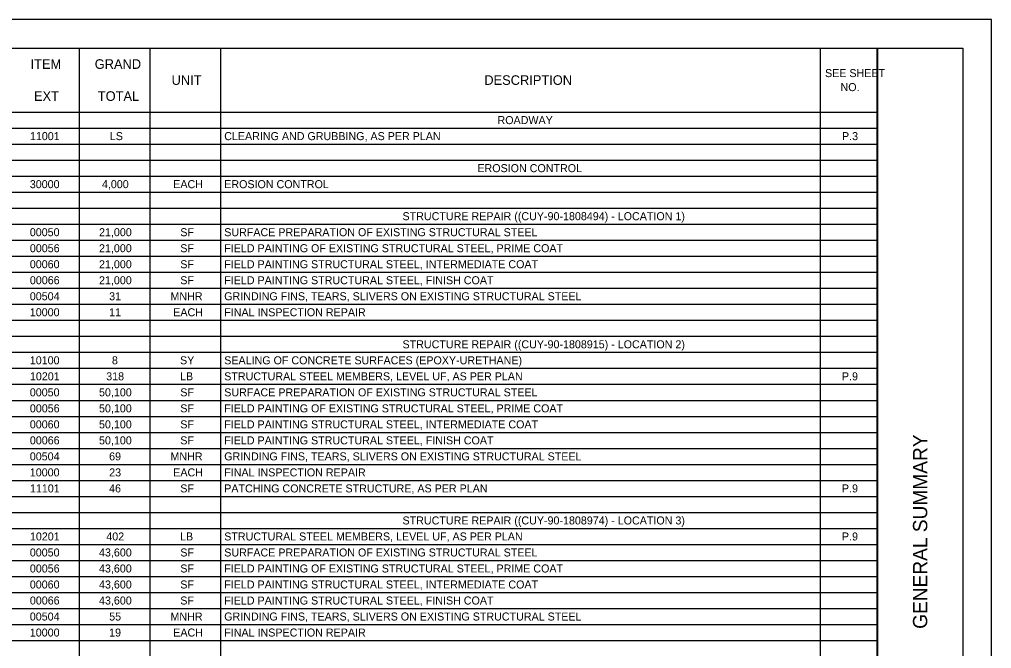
# Model space of a CAD drawing. Extents: x 0 to 34, y 0 to 22.
# Drawn here: x 16.99 to 34, y 11 to 22 of the extents above; entities that cross this region are included whole.
import ezdxf

# ---------------------------------------------------------------- set-up
doc = ezdxf.new("R2010")
doc.units = 0
for name, color, linetype in [('SH_Border', 7, 'Continuous'), ('SH_Cut_Line', 7, 'Continuous'), ('SH_Data', 7, 'Continuous'), ('SH_Text', 7, 'Continuous')]:
    doc.layers.add(name, color=color, linetype=linetype)

msp = doc.modelspace()

# ---------------------------------------------------------------- linework, layer by layer
at = {"layer": 'SH_Border'}
msp.add_line((32, 0.5), (32, 21.5), dxfattribs=at)
msp.add_lwpolyline([(1.5, 21.5), (33.5, 21.5), (33.5, 0.5), (1.5, 0.5)], close=True, dxfattribs=at)
at = {"layer": 'SH_Cut_Line'}
msp.add_lwpolyline([(0, 0), (34, 0), (34, 22), (0, 22)], close=True, dxfattribs=at)
at = {"layer": 'SH_Data'}
for p, q in [((1.5, 21.5), (32.004, 21.5)), ((18.036, 21.5), (18.036, 0.5)), ((19.272, 21.5), (19.272, 0.5)), ((20.507, 21.5), (20.507, 0.5)), ((30.999, 21.5), (30.999, 0.5)), ((32.004, 21.5), (32.004, 0.5)), ((1.5, 20.38), (32.004, 20.38)), ((1.5, 20.1), (32.004, 20.1)), ((1.5, 19.82), (32.004, 19.82)), ((1.5, 19.54), (32.004, 19.54)), ((1.5, 19.26), (32.004, 19.26)), ((1.5, 18.98), (32.004, 18.98)), ((1.5, 18.7), (32.004, 18.7)), ((1.5, 18.42), (32.004, 18.42)), ((1.5, 18.14), (32.004, 18.14)), ((1.5, 17.86), (32.004, 17.86)), ((1.5, 17.58), (32.004, 17.58)), ((1.5, 17.3), (32.004, 17.3)), ((1.5, 17.02), (32.004, 17.02)), ((1.5, 16.74), (32.004, 16.74)), ((1.5, 16.46), (32.004, 16.46)), ((1.5, 16.18), (32.004, 16.18)), ((1.5, 15.9), (32.004, 15.9)), ((1.5, 15.62), (32.004, 15.62)), ((1.5, 15.34), (32.004, 15.34)), ((1.5, 15.06), (32.004, 15.06)), ((1.5, 14.78), (32.004, 14.78)), ((1.5, 14.5), (32.004, 14.5)), ((1.5, 14.22), (32.004, 14.22)), ((1.5, 13.94), (32.004, 13.94)), ((1.5, 13.66), (32.004, 13.66)), ((1.5, 13.38), (32.004, 13.38)), ((1.5, 13.1), (32.004, 13.1)), ((1.5, 12.82), (32.004, 12.82)), ((1.5, 12.54), (32.004, 12.54)), ((1.5, 12.26), (32.004, 12.26)), ((1.5, 11.98), (32.004, 11.98)), ((1.5, 11.7), (32.004, 11.7)), ((1.5, 11.42), (32.004, 11.42)), ((1.5, 11.14), (32.004, 11.14))]:
    msp.add_line(p, q, dxfattribs=at)

# ---------------------------------------------------------------- texts
msp.add_text('GENERAL SUMMARY', height=0.25, rotation=90, dxfattribs=at).set_placement((32.875, 11.344))
at = {"layer": 'SH_Text'}
for s, height, p in [('ITEM', 0.168, (17.184, 21.136)), ('GRAND', 0.168, (18.307, 21.136)), ('SEE SHEET ', 0.14, (31.086, 20.992)), ('UNIT', 0.168, (19.652, 20.856)), ('DESCRIPTION', 0.168, (25.124, 20.856)), ('NO.', 0.14, (31.357, 20.747)), ('EXT', 0.168, (17.244, 20.576)), ('TOTAL', 0.168, (18.361, 20.576)), ('ROADWAY', 0.14, (25.355, 20.17)), ('11001', 0.14, (17.173, 19.89)), ('LS', 0.14, (18.572, 19.89)), ('CLEARING AND GRUBBING, AS PER PLAN', 0.14, (20.573, 19.89)), ('P.3', 0.14, (31.383, 19.89)), ('EROSION CONTROL', 0.14, (25.003, 19.33)), ('30000', 0.14, (17.171, 19.05)), ('4,000', 0.14, (18.433, 19.05)), ('EACH', 0.14, (19.681, 19.05)), ('EROSION CONTROL', 0.14, (20.573, 19.05)), ('STRUCTURE REPAIR ((CUY-90-1808494) - LOCATION 1)', 0.14, (23.693, 18.49)), ('00050', 0.14, (17.171, 18.21)), ('21,000', 0.14, (18.382, 18.21)), ('SF', 0.14, (19.804, 18.21)), ('SURFACE PREPARATION OF EXISTING STRUCTURAL STEEL', 0.14, (20.573, 18.21)), ('00056', 0.14, (17.172, 17.93)), ('21,000', 0.14, (18.382, 17.93)), ('SF', 0.14, (19.804, 17.93)), ('FIELD PAINTING OF EXISTING STRUCTURAL STEEL, PRIME COAT', 0.14, (20.573, 17.93)), ('00060', 0.14, (17.171, 17.65)), ('21,000', 0.14, (18.382, 17.65)), ('SF', 0.14, (19.804, 17.65)), ('FIELD PAINTING STRUCTURAL STEEL, INTERMEDIATE COAT', 0.14, (20.573, 17.65)), ('00066', 0.14, (17.172, 17.37)), ('21,000', 0.14, (18.382, 17.37)), ('SF', 0.14, (19.804, 17.37)), ('FIELD PAINTING STRUCTURAL STEEL, FINISH COAT', 0.14, (20.573, 17.37)), ('00504', 0.14, (17.171, 17.09)), ('31', 0.14, (18.559, 17.09)), ('MNHR', 0.14, (19.632, 17.09)), ('GRINDING FINS, TEARS, SLIVERS ON EXISTING STRUCTURAL STEEL', 0.14, (20.573, 17.09)), ('10000', 0.14, (17.171, 16.81)), ('11', 0.14, (18.559, 16.81)), ('EACH', 0.14, (19.681, 16.81)), ('FINAL INSPECTION REPAIR', 0.14, (20.573, 16.81)), ('STRUCTURE REPAIR ((CUY-90-1808915) - LOCATION 2)', 0.14, (23.693, 16.25)), ('10100', 0.14, (17.171, 15.97)), ('8', 0.14, (18.608, 15.97)), ('SY', 0.14, (19.8, 15.97)), ('SEALING OF CONCRETE SURFACES (EPOXY-URETHANE)', 0.14, (20.573, 15.97)), ('10201', 0.14, (17.173, 15.69)), ('318', 0.14, (18.508, 15.69)), ('LB', 0.14, (19.8, 15.69)), ('STRUCTURAL STEEL MEMBERS, LEVEL UF, AS PER PLAN', 0.14, (20.573, 15.69)), ('P.9', 0.14, (31.382, 15.69)), ('00050', 0.14, (17.171, 15.41)), ('50,100', 0.14, (18.382, 15.41)), ('SF', 0.14, (19.804, 15.41)), ('SURFACE PREPARATION OF EXISTING STRUCTURAL STEEL', 0.14, (20.573, 15.41)), ('00056', 0.14, (17.172, 15.13)), ('50,100', 0.14, (18.382, 15.13)), ('SF', 0.14, (19.804, 15.13)), ('FIELD PAINTING OF EXISTING STRUCTURAL STEEL, PRIME COAT', 0.14, (20.573, 15.13)), ('00060', 0.14, (17.171, 14.85)), ('50,100', 0.14, (18.382, 14.85)), ('SF', 0.14, (19.804, 14.85)), ('FIELD PAINTING STRUCTURAL STEEL, INTERMEDIATE COAT', 0.14, (20.573, 14.85)), ('00066', 0.14, (17.172, 14.57)), ('50,100', 0.14, (18.382, 14.57)), ('SF', 0.14, (19.804, 14.57)), ('FIELD PAINTING STRUCTURAL STEEL, FINISH COAT', 0.14, (20.573, 14.57)), ('00504', 0.14, (17.171, 14.29)), ('69', 0.14, (18.559, 14.29)), ('MNHR', 0.14, (19.632, 14.29)), ('GRINDING FINS, TEARS, SLIVERS ON EXISTING STRUCTURAL STEEL', 0.14, (20.573, 14.29)), ('10000', 0.14, (17.171, 14.01)), ('23', 0.14, (18.56, 14.01)), ('EACH', 0.14, (19.681, 14.01)), ('FINAL INSPECTION REPAIR', 0.14, (20.573, 14.01)), ('11101', 0.14, (17.173, 13.73)), ('46', 0.14, (18.558, 13.73)), ('SF', 0.14, (19.804, 13.73)), ('PATCHING CONCRETE STRUCTURE, AS PER PLAN', 0.14, (20.573, 13.73)), ('P.9', 0.14, (31.382, 13.73)), ('STRUCTURE REPAIR ((CUY-90-1808974) - LOCATION 3)', 0.14, (23.693, 13.17)), ('10201', 0.14, (17.173, 12.89)), ('402', 0.14, (18.51, 12.89)), ('LB', 0.14, (19.8, 12.89)), ('STRUCTURAL STEEL MEMBERS, LEVEL UF, AS PER PLAN', 0.14, (20.573, 12.89)), ('P.9', 0.14, (31.382, 12.89)), ('00050', 0.14, (17.171, 12.61)), ('43,600', 0.14, (18.382, 12.61)), ('SF', 0.14, (19.804, 12.61)), ('SURFACE PREPARATION OF EXISTING STRUCTURAL STEEL', 0.14, (20.573, 12.61)), ('00056', 0.14, (17.172, 12.33)), ('43,600', 0.14, (18.382, 12.33)), ('SF', 0.14, (19.804, 12.33)), ('FIELD PAINTING OF EXISTING STRUCTURAL STEEL, PRIME COAT', 0.14, (20.573, 12.33)), ('00060', 0.14, (17.171, 12.05)), ('43,600', 0.14, (18.382, 12.05)), ('SF', 0.14, (19.804, 12.05)), ('FIELD PAINTING STRUCTURAL STEEL, INTERMEDIATE COAT', 0.14, (20.573, 12.05)), ('00066', 0.14, (17.172, 11.77)), ('43,600', 0.14, (18.382, 11.77)), ('SF', 0.14, (19.804, 11.77)), ('FIELD PAINTING STRUCTURAL STEEL, FINISH COAT', 0.14, (20.573, 11.77)), ('00504', 0.14, (17.171, 11.49)), ('55', 0.14, (18.56, 11.49)), ('MNHR', 0.14, (19.632, 11.49)), ('GRINDING FINS, TEARS, SLIVERS ON EXISTING STRUCTURAL STEEL', 0.14, (20.573, 11.49)), ('10000', 0.14, (17.171, 11.21)), ('19', 0.14, (18.559, 11.21)), ('EACH', 0.14, (19.681, 11.21)), ('FINAL INSPECTION REPAIR', 0.14, (20.573, 11.21))]:
    msp.add_text(s, height=height, dxfattribs=at).set_placement(p)

doc.saveas('drawing.dxf')
